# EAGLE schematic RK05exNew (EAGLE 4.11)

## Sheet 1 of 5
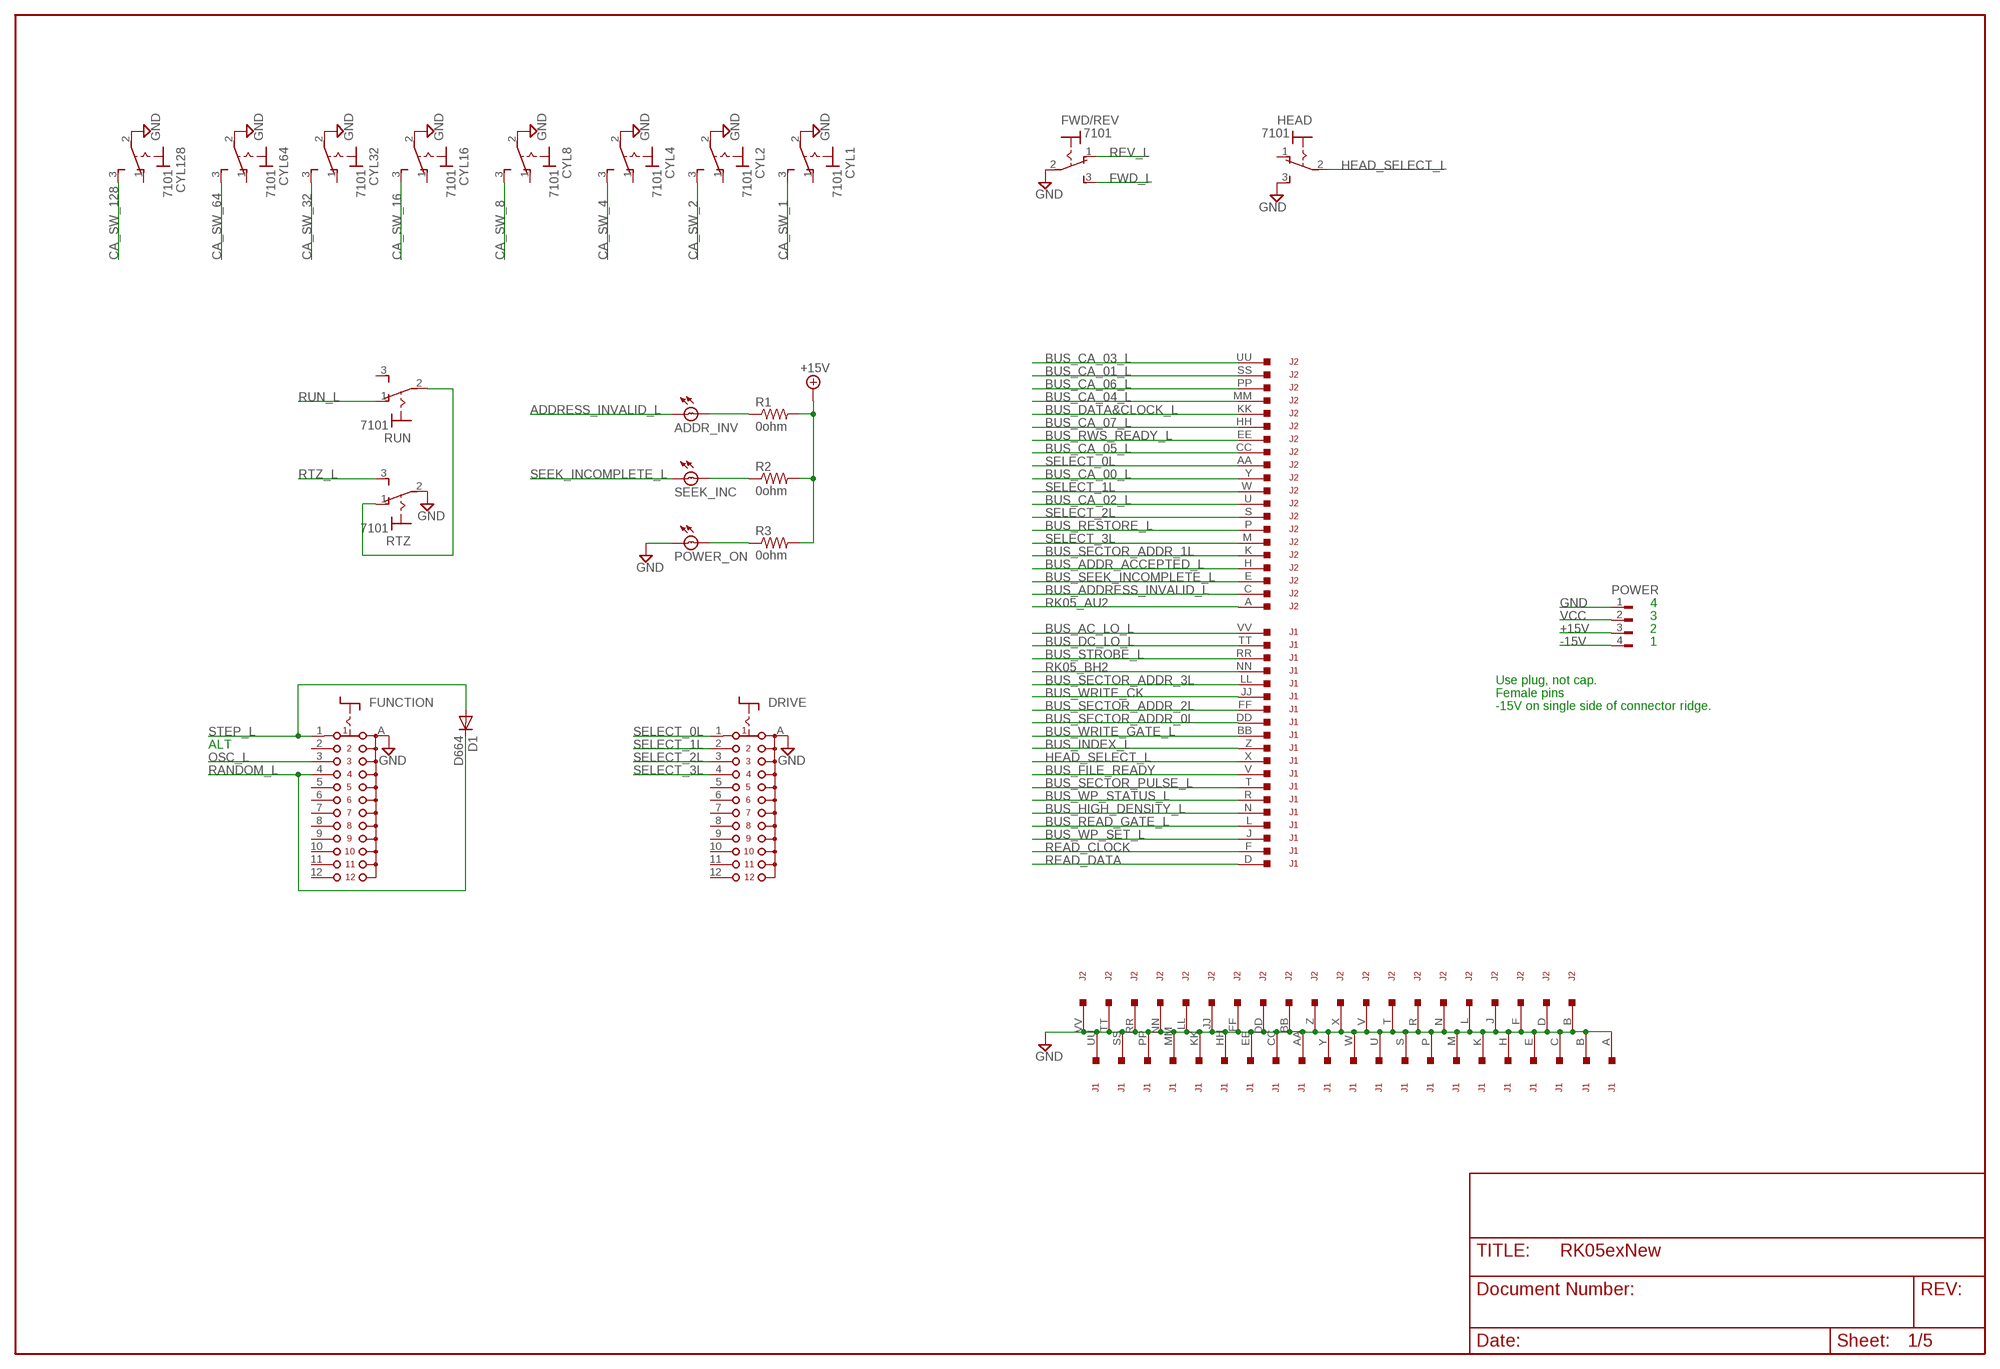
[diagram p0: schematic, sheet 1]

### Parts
ADDR_INV  BULB  [BULB]
CYL1  7101  710X  [7109MD9V3]
CYL2  7101  710X  [7109MD9V3]
CYL4  7101  710X  [7109MD9V3]
CYL8  7101  710X  [7109MD9V3]
CYL16  7101  710X  [7109MD9V3]
CYL32  7101  710X  [7109MD9V3]
CYL64  7101  710X  [7109MD9V3]
CYL128  7101  710X  [7109MD9V3]
D1  D664  1N4148  [DO35-10]
DRIVE  CK101X12  [CK101X12]
FUNCTION  CK101X12  [CK101X12]
FWD/REV  7101  710X  [7109MD9V3]
HEAD  7101  710X  [7109MD9V3]
J1  DEC40PINSV  [DEC40PINV]
J2  DEC40PINSV  [DEC40PINV]
POWER  FLOPPY-4  [FLOPPY-4]
POWER_ON  BULB  [BULB]
R1  0ohm  R-US_0207/10  [0207/10]
R2  0ohm  R-US_0207/10  [0207/10]
R3  0ohm  R-US_0207/10  [0207/10]
RTZ  7101  710X  [7109MD9V3]
RUN  7101  710X  [7109MD9V3]
SEEK_INC  BULB  [BULB]

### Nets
+15V: POWER.3 R1.2 R2.2 R3.2 ; also sheet 3
-15V: POWER.4 ; also sheet 3
ADDRESS_INVALID_L: ADDR_INV.B ; also sheet 3
BUS_AC_LO_L: J1.VV ; also sheet 5
BUS_ADDR_ACCEPTED_L: J2.H ; also sheet 5
BUS_ADDRESS_INVALID_L: J2.C ; also sheet 3,5
BUS_CA_00_L: J2.Y ; also sheet 4,5
BUS_CA_01_L: J2.SS ; also sheet 4,5
BUS_CA_02_L: J2.U ; also sheet 4,5
BUS_CA_03_L: J2.UU ; also sheet 4,5
BUS_CA_04_L: J2.MM ; also sheet 4,5
BUS_CA_05_L: J2.CC ; also sheet 4,5
BUS_CA_06_L: J2.PP ; also sheet 4,5
BUS_CA_07_L: J2.HH ; also sheet 4,5
BUS_DATA&CLOCK_L: J2.KK ; also sheet 2,5
BUS_DC_LO_L: J1.TT ; also sheet 5
BUS_FILE_READY: J1.V ; also sheet 5
BUS_HIGH_DENSITY_L: J1.N ; also sheet 5
BUS_INDEX_L: J1.Z ; also sheet 2,5
BUS_READ_GATE_L: J1.L ; also sheet 5
BUS_RESTORE_L: J2.P ; also sheet 3,5
BUS_RWS_READY_L: J2.EE ; also sheet 3,5
BUS_SECTOR_ADDR_0L: J1.DD ; also sheet 2,5
BUS_SECTOR_ADDR_1L: J2.K ; also sheet 2,5
BUS_SECTOR_ADDR_2L: J1.FF ; also sheet 2,5
BUS_SECTOR_ADDR_3L: J1.LL ; also sheet 2,5
BUS_SECTOR_PULSE_L: J1.T ; also sheet 5
BUS_SEEK_INCOMPLETE_L: J2.E ; also sheet 3,5
BUS_STROBE_L: J1.RR ; also sheet 3,5
BUS_WP_SET_L: J1.J ; also sheet 5
BUS_WP_STATUS_L: J1.R ; also sheet 5
BUS_WRITE_CK: J1.JJ ; also sheet 5
BUS_WRITE_GATE_L: J1.BB ; also sheet 2,5
CA_SW_1: CYL1.3(S) ; also sheet 4
CA_SW_2: CYL2.3(S) ; also sheet 4
CA_SW_4: CYL4.3(S) ; also sheet 4
CA_SW_8: CYL8.3(S) ; also sheet 4
CA_SW_16: CYL16.3(S) ; also sheet 4
CA_SW_32: CYL32.3(S) ; also sheet 4
CA_SW_64: CYL64.3(S) ; also sheet 4
CA_SW_128: CYL128.3(S) ; also sheet 4
FWD_L: FWD/REV.3(S) ; also sheet 3
GND: CYL1.2(P) CYL2.2(P) CYL4.2(P) CYL8.2(P) CYL16.2(P) CYL32.2(P) CYL64.2(P) CYL128.2(P) DRIVE.A FUNCTION.A FWD/REV.2(P) HEAD.3(S) J1.A J1.AA J1.B J1.C J1.CC J1.E J1.EE J1.H J1.HH J1.K J1.KK J1.M J1.MM J1.P J1.PP J1.S J1.SS J1.U J1.UU J1.W J1.Y J2.B J2.BB J2.D J2.DD J2.F J2.FF J2.J J2.JJ J2.L J2.LL J2.N J2.NN J2.R J2.RR J2.T J2.TT J2.V J2.VV J2.X J2.Z POWER.1 POWER_ON.B RTZ.2(P) ; also sheet 2,3,4,5
HEAD_SELECT_L: HEAD.2(P) J1.X ; also sheet 5
N$30: RTZ.1(O) RUN.2(P)
N$37: ADDR_INV.A R1.1
N$38: R2.1 SEEK_INC.A
N$39: POWER_ON.A R3.1
OSC_L: FUNCTION.3 ; also sheet 3
RANDOM_L: D1.C FUNCTION.4 ; also sheet 3
READ_CLOCK: J1.F ; also sheet 5
READ_DATA: J1.D ; also sheet 5
REV_L: FWD/REV.1(O) ; also sheet 3
RK05_AU2: J2.A ; also sheet 5
RK05_BH2: J1.NN ; also sheet 5
RTZ_L: RTZ.3(S) ; also sheet 3
RUN_L: RUN.1(O) ; also sheet 3
SEEK_INCOMPLETE_L: SEEK_INC.B ; also sheet 3
SELECT_0L: DRIVE.1 J2.AA ; also sheet 5
SELECT_1L: DRIVE.2 J2.W ; also sheet 5
SELECT_2L: DRIVE.3 J2.S ; also sheet 5
SELECT_3L: DRIVE.4 J2.M ; also sheet 5
STEP_L: D1.A FUNCTION.1 ; also sheet 3
VCC: POWER.2 ; also sheet 2,3,4,5
Unconnected: CYL1.1(O) CYL2.1(O) CYL4.1(O) CYL8.1(O) CYL16.1(O) CYL32.1(O) CYL64.1(O) CYL128.1(O) DRIVE.5 DRIVE.6 DRIVE.7 DRIVE.8 DRIVE.9 DRIVE.10 DRIVE.11 DRIVE.12 FUNCTION.2 FUNCTION.5 FUNCTION.6 FUNCTION.7 FUNCTION.8 FUNCTION.9 FUNCTION.10 FUNCTION.11 FUNCTION.12 HEAD.1(O) RUN.3(S)

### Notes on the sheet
- 4
- 3
- 2
- 1
- Use plug, not cap.
- Female pins
- -15V on single side of connector ridge.
- ALT

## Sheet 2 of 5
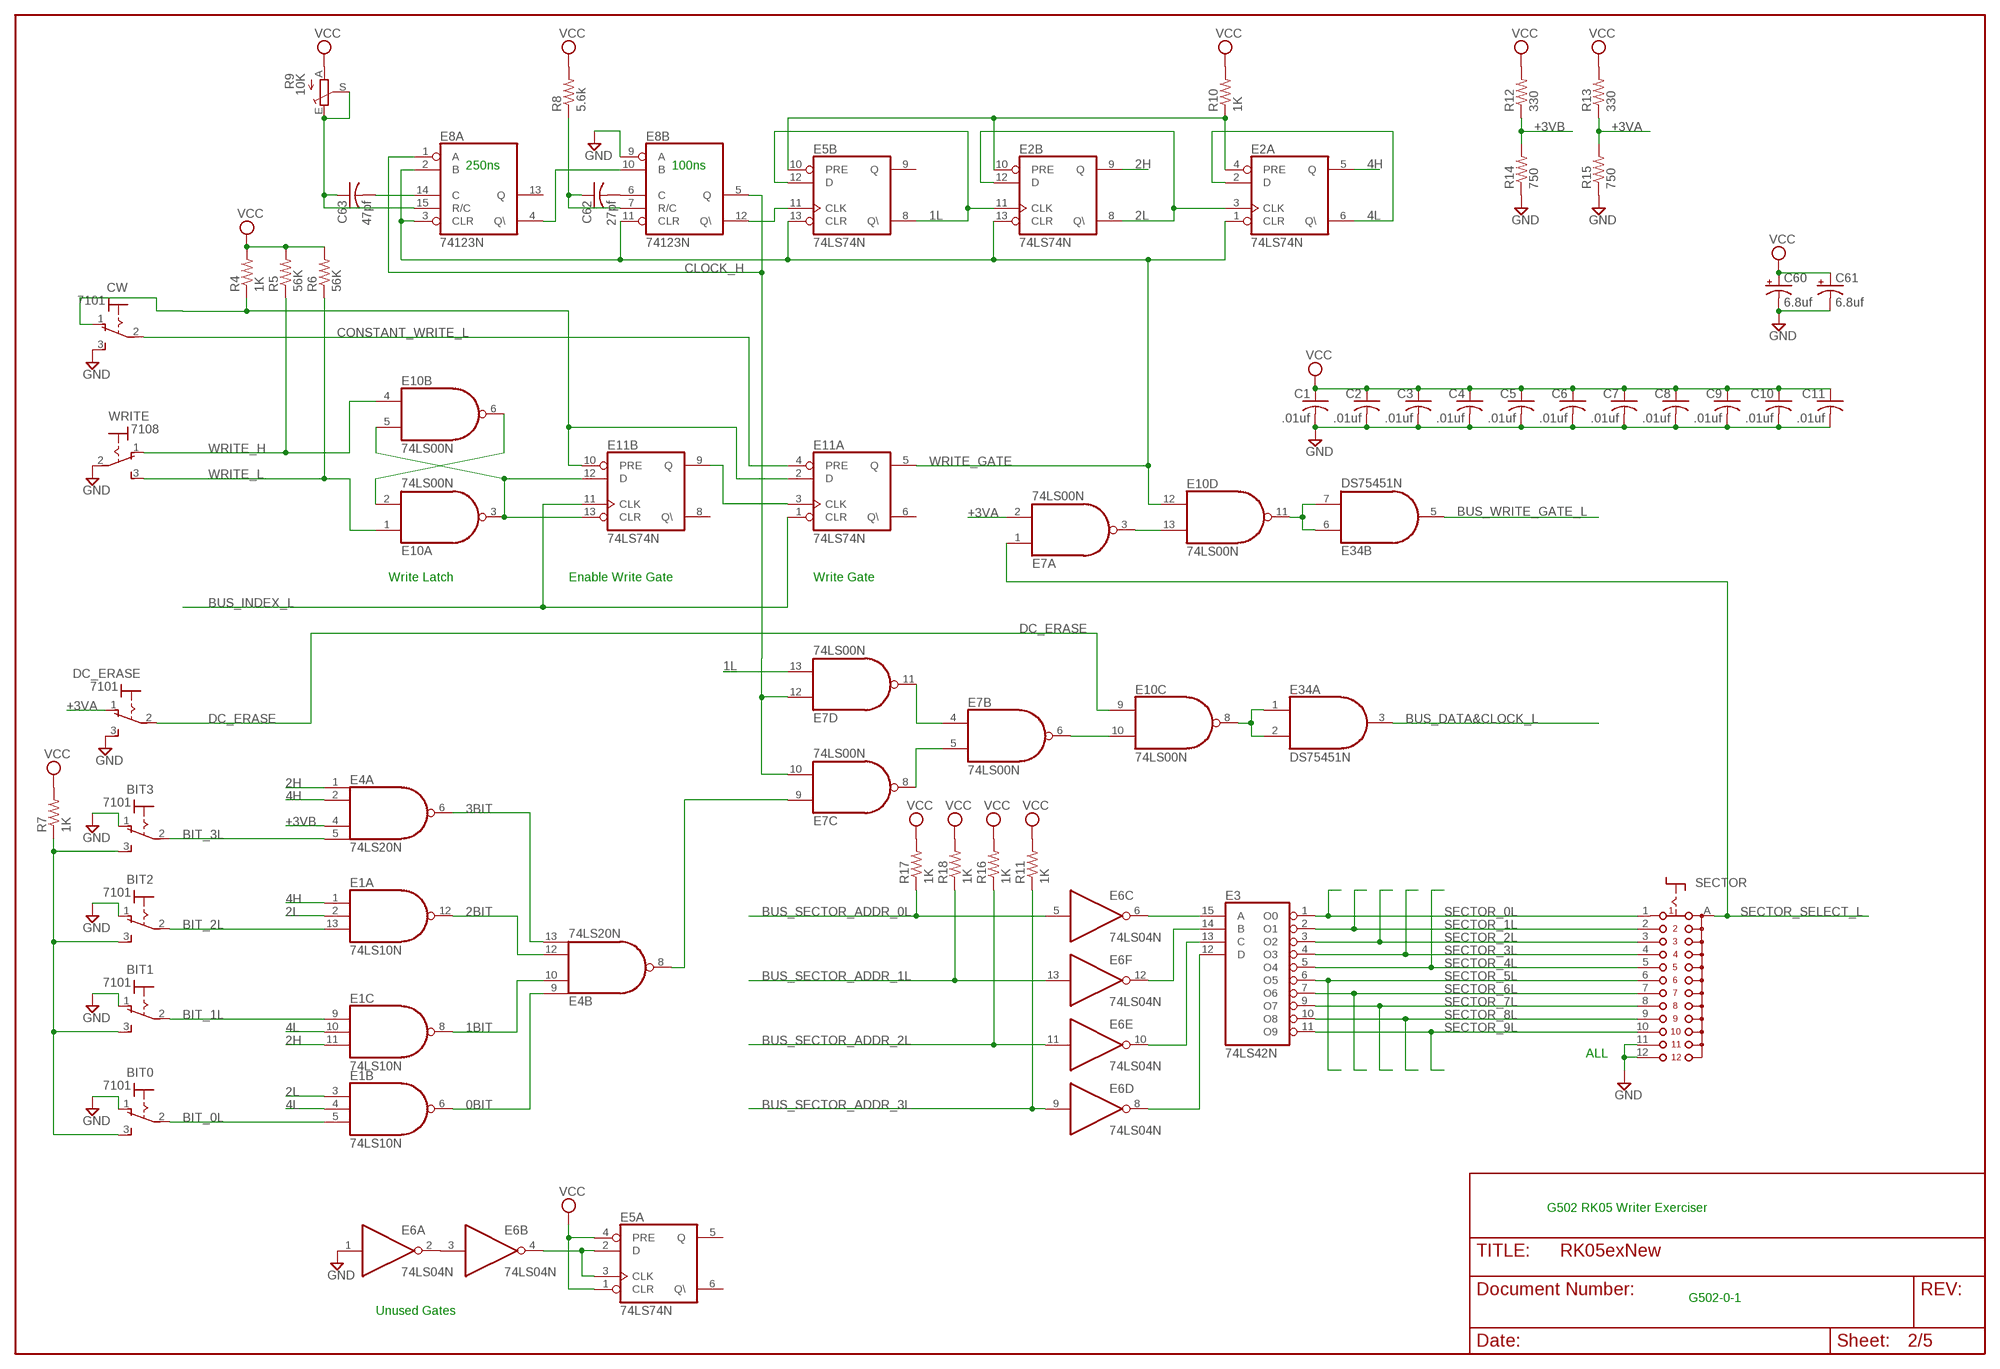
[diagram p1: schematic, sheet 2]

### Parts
BIT0  7101  710X  [7109MD9V3]
BIT1  7101  710X  [7109MD9V3]
BIT2  7101  710X  [7109MD9V3]
BIT3  7101  710X  [7109MD9V3]
C1  .01uf  C-US075-032X103  [C075-032X103]
C2  .01uf  C-US075-032X103  [C075-032X103]
C3  .01uf  C-US075-032X103  [C075-032X103]
C4  .01uf  C-US075-032X103  [C075-032X103]
C5  .01uf  C-US075-032X103  [C075-032X103]
C6  .01uf  C-US075-032X103  [C075-032X103]
C7  .01uf  C-US075-032X103  [C075-032X103]
C8  .01uf  C-US075-032X103  [C075-032X103]
C9  .01uf  C-US075-032X103  [C075-032X103]
C10  .01uf  C-US075-032X103  [C075-032X103]
C11  .01uf  C-US075-032X103  [C075-032X103]
C60  6.8uf  CPOL-USE15-5AXIAL  [E15-5]
C61  6.8uf  CPOL-USE15-5AXIAL  [E15-5]
C62  27pf  C-US075-032X103  [C075-032X103]
C63  47pf  C-US075-032X103  [C075-032X103]
CW  7101  710X  [7109MD9V3]
DC_ERASE  7101  710X  [7109MD9V3]
E1  74LS10N  [DIL14]
E2  74LS74N  [DIL14]
E3  74LS42N  [DIL16]
E4  74LS20N  [DIL14]
E5  74LS74N  [DIL14]
E6  74LS04N  [DIL14]
E7  74LS00N  [DIL14]
E8  74123N  [DIL16]
E10  74LS00N  [DIL14]
E11  74LS74N  [DIL14]
E34  DS75451N  [DIL08]
R4  1K  R-US_0207/10  [0207/10]
R5  56K  R-US_0207/10  [0207/10]
R6  56K  R-US_0207/10  [0207/10]
R7  1K  R-US_0207/10  [0207/10]
R8  5.6k  R-US_0207/10  [0207/10]
R9  10K  TRIM_EU-B90P  [SP19L]
R10  1K  R-US_0207/10  [0207/10]
R11  1K  R-US_0207/10  [0207/10]
R12  330  R-US_0207/10  [0207/10]
R13  330  R-US_0207/10  [0207/10]
R14  750  R-US_0207/10  [0207/10]
R15  750  R-US_0207/10  [0207/10]
R16  1K  R-US_0207/10  [0207/10]
R17  1K  R-US_0207/10  [0207/10]
R18  1K  R-US_0207/10  [0207/10]
SECTOR  CK101X12  [CK101X12]
WRITE  7108  710X  [7109MD9V3]

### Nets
0BIT: E1.6(B:O) E4.9(B:I0)
1.44MHZ: E5.11(B:CLK) E8.12(B:Q\)
1BIT: E1.8(C:O) E4.10(B:I1)
1L: E2.11(B:CLK) E5.8(B:Q\) E5.12(B:D) E7.13(D:I1)
2.88MHZ: E8.4(A:Q\) E8.10(B:B)
2BIT: E1.12(A:O) E4.12(B:I2)
2H: E1.11(C:I2) E2.9(B:Q) E4.1(A:I0)
2L: E1.2(A:I1) E1.3(B:I0) E2.3(A:CLK) E2.8(B:Q\) E2.12(B:D)
3BIT: E4.6(A:O) E4.13(B:I3)
4H: E1.1(A:I0) E2.5(A:Q) E4.2(A:I1)
4L: E1.4(B:I1) E1.10(C:I1) E2.2(A:D) E2.6(A:Q\)
+3VA: DC_ERASE.1(O) E7.2(A:I1) R13.1 R15.2
+3VB: E4.4(A:I2) R12.1 R14.2
+3VC: CW.1(O) E11.2(A:D) E11.10(B:PRE) R4.1
BIT_0L: BIT0.2(P) E1.5(B:I2)
BIT_1L: BIT1.2(P) E1.9(C:I0)
BIT_2L: BIT2.2(P) E1.13(A:I2)
BIT_3L: BIT3.2(P) E4.5(A:I3)
BUS_DATA&CLOCK_L: E34.3(A:O) ; also sheet 1,5
BUS_INDEX_L: E11.1(A:CLR) E11.11(B:CLK) ; also sheet 1,5
BUS_SECTOR_ADDR_0L: E6.5(C:I) R17.1 ; also sheet 1,5
BUS_SECTOR_ADDR_1L: E6.13(F:I) R18.1 ; also sheet 1,5
BUS_SECTOR_ADDR_2L: E6.11(E:I) R16.1 ; also sheet 1,5
BUS_SECTOR_ADDR_3L: E6.9(D:I) R11.1 ; also sheet 1,5
BUS_WRITE_GATE_L: E34.5(B:O) ; also sheet 1,5
CLOCK_H: E7.10(C:I1) E7.12(D:I0) E8.1(A:A) E8.5(B:Q)
CONSTANT_WRITE_L: CW.2(P) E11.4(A:PRE)
DATA_BITS: BIT0.3(S) BIT1.3(S) BIT2.3(S) BIT3.3(S) R7.1
DC_ERASE: DC_ERASE.2(P) E10.9(C:I0)
GND: BIT0.1(O) BIT1.1(O) BIT2.1(O) BIT3.1(O) C1.2 C2.2 C3.2 C4.2 C5.2 C6.2 C7.2 C8.2 C9.2 C10.2 C11.2 C60.- C61.- CW.3(S) DC_ERASE.3(S) E6.1(A:I) E8.9(B:A) R14.1 R15.1 SECTOR.11 SECTOR.12 WRITE.2(P) ; also sheet 1,3,4,5
N$2: E7.6(B:O) E10.10(C:I1)
N$3: E10.3(A:O) E10.5(B:I1) E11.12(B:D) E11.13(B:CLR)
N$4: E10.2(A:I1) E10.6(B:O)
N$5: E2.4(A:PRE) E2.10(B:PRE) E5.10(B:PRE) R10.1
N$6: E7.4(B:I0) E7.11(D:O)
N$7: E7.5(B:I1) E7.8(C:O)
N$8: E11.3(A:CLK) E11.9(B:Q)
N$9: E4.8(B:O) E7.9(C:I0)
N$11: C63.2 E8.14(A:C)
N$12: C62.2 E8.6(B:C)
N$13: C63.1 E8.15(A:R/C) R9.E R9.S
N$14: C62.1 E8.7(B:R/C) R8.1
N$15: E7.3(A:O) E10.13(D:I1)
N$29: E3.15(A) E6.6(C:O)
N$31: E3.14(B) E6.12(F:O)
N$32: E3.13(C) E6.10(E:O)
N$33: E3.12(D) E6.8(D:O)
N$34: E6.2(A:O) E6.3(B:I)
N$36: E5.2(A:D) E5.3(A:CLK) E6.4(B:O)
N$45: E10.8(C:O) E34.1(A:I0) E34.2(A:I1)
N$49: E10.11(D:O) E34.6(B:I0) E34.7(B:I1)
SECTOR_0L: E3.1(O0) SECTOR.1
SECTOR_1L: E3.2(O1) SECTOR.2
SECTOR_2L: E3.3(O2) SECTOR.3
SECTOR_3L: E3.4(O3) SECTOR.4
SECTOR_4L: E3.5(O4) SECTOR.5
SECTOR_5L: E3.6(O5) SECTOR.6
SECTOR_6L: E3.7(O6) SECTOR.7
SECTOR_7L: E3.9(O7) SECTOR.8
SECTOR_8L: E3.10(O8) SECTOR.9
SECTOR_9L: E3.11(O9) SECTOR.10
SECTOR_SELECT_L: E7.1(A:I0) SECTOR.A
VCC: C1.1 C2.1 C3.1 C4.1 C5.1 C6.1 C7.1 C8.1 C9.1 C10.1 C11.1 C60.+ C61.+ E5.1(A:CLR) E5.4(A:PRE) R4.2 R5.2 R6.2 R7.2 R8.2 R9.A R10.2 R11.2 R12.2 R13.2 R16.2 R17.2 R18.2 ; also sheet 1,3,4,5
WRITE_GATE: E2.1(A:CLR) E2.13(B:CLR) E5.13(B:CLR) E8.2(A:B) E8.3(A:CLR) E8.11(B:CLR) E10.12(D:I0) E11.5(A:Q)
WRITE_H: E10.4(B:I0) R5.1 WRITE.1(O)
WRITE_L: E10.1(A:I0) R6.1 WRITE.3(S)
Unconnected: E5.5(A:Q) E5.6(A:Q\) E5.9(B:Q) E8.13(A:Q) E11.6(A:Q\) E11.8(B:Q\)

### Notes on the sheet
- 250ns | 100ns
- Write Latch | Enable Write Gate | Write Gate
- ALL
- G502 RK05 Writer Exerciser
- G502-0-1
- Unused Gates

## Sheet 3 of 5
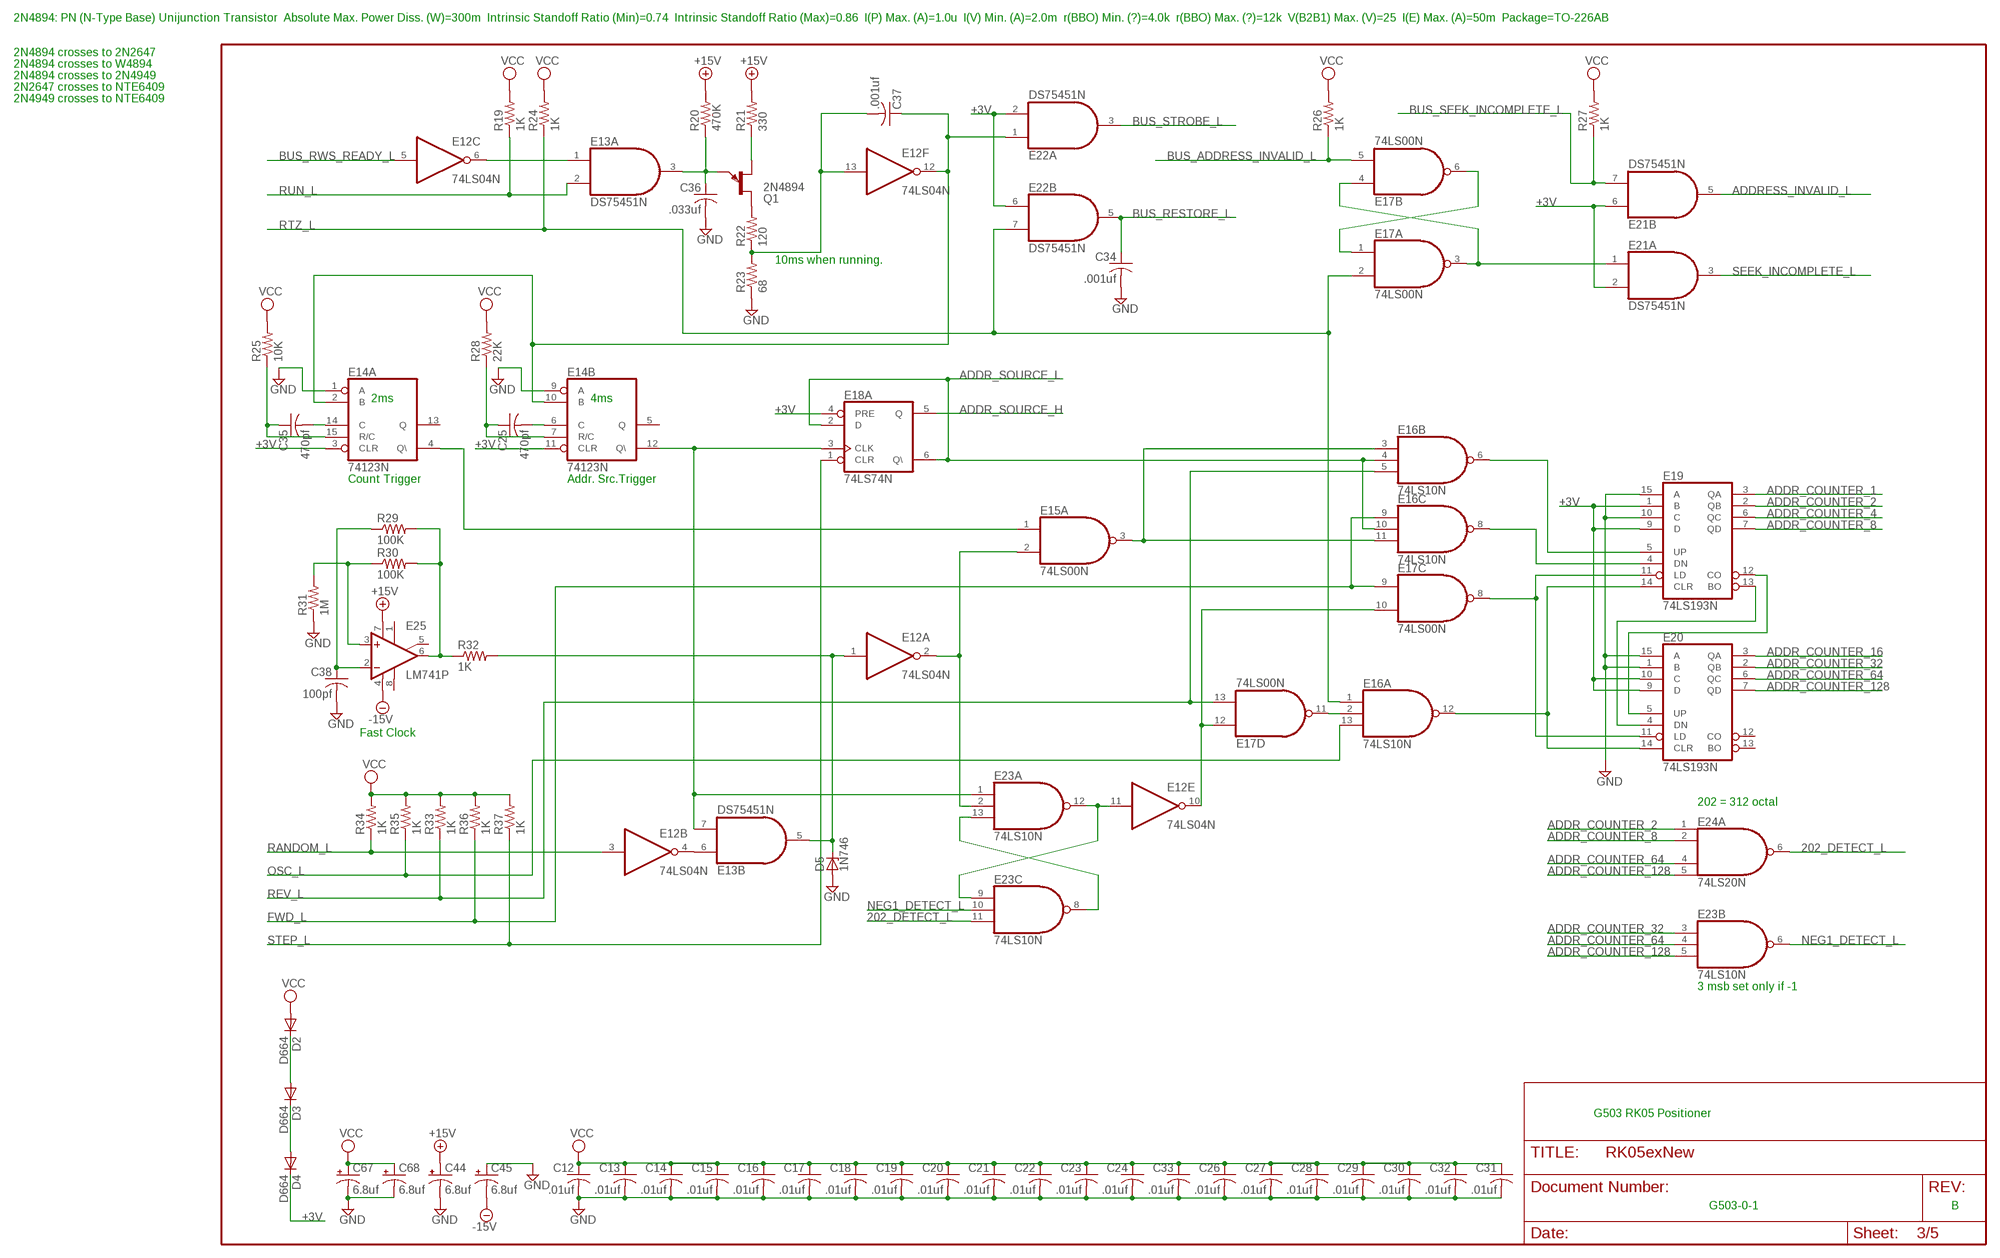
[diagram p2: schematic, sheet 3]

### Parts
C12  .01uf  C-US075-032X103  [C075-032X103]
C13  .01uf  C-US075-032X103  [C075-032X103]
C14  .01uf  C-US075-032X103  [C075-032X103]
C15  .01uf  C-US075-032X103  [C075-032X103]
C16  .01uf  C-US075-032X103  [C075-032X103]
C17  .01uf  C-US075-032X103  [C075-032X103]
C18  .01uf  C-US075-032X103  [C075-032X103]
C19  .01uf  C-US075-032X103  [C075-032X103]
C20  .01uf  C-US075-032X103  [C075-032X103]
C21  .01uf  C-US075-032X103  [C075-032X103]
C22  .01uf  C-US075-032X103  [C075-032X103]
C23  .01uf  C-US075-032X103  [C075-032X103]
C24  .01uf  C-US075-032X103  [C075-032X103]
C25  470pf  C-US075-032X103  [C075-032X103]
C26  .01uf  C-US075-032X103  [C075-032X103]
C27  .01uf  C-US075-032X103  [C075-032X103]
C28  .01uf  C-US075-032X103  [C075-032X103]
C29  .01uf  C-US075-032X103  [C075-032X103]
C30  .01uf  C-US075-032X103  [C075-032X103]
C31  .01uf  C-US075-032X103  [C075-032X103]
C32  .01uf  C-US075-032X103  [C075-032X103]
C33  .01uf  C-US075-032X103  [C075-032X103]
C34  .001uf  C-US075-032X103  [C075-032X103]
C35  470pf  C-US075-032X103  [C075-032X103]
C36  .033uf  C-US075-032X103  [C075-032X103]
C37  .001uf  C-US075-032X103  [C075-032X103]
C38  100pf  C-US075-032X103  [C075-032X103]
C44  6.8uf  CPOL-USE15-5AXIAL  [E15-5]
C45  6.8uf  CPOL-USE15-5AXIAL  [E15-5]
C67  6.8uf  CPOL-USE15-5AXIAL  [E15-5]
C68  6.8uf  CPOL-USE15-5AXIAL  [E15-5]
D2  D664  1N4148  [DO35-10]
D3  D664  1N4148  [DO35-10]
D4  D664  1N4148  [DO35-10]
D5  1N746  ZENER-DIODEDO35Z10  [DO35Z10]
E12  74LS04N  [DIL14]
E13  DS75451N  [DIL08]
E14  74123N  [DIL16]
E15  74LS00N  [DIL14]
E16  74LS10N  [DIL14]
E17  74LS00N  [DIL14]
E18  74LS74N  [DIL14]
E19  74LS193N  [DIL16]
E20  74LS193N  [DIL16]
E21  DS75451N  [DIL08]
E22  DS75451N  [DIL08]
E23  74LS10N  [DIL14]
E24  74LS20N  [DIL14]
E25  LM741P  [DIL08]
Q1  2N4894  2N4870  [TO92E]
R19  1K  R-US_0207/10  [0207/10]
R20  470K  R-US_0207/10  [0207/10]
R21  330  R-US_0207/10  [0207/10]
R22  120  R-US_0207/10  [0207/10]
R23  68  R-US_0207/10  [0207/10]
R24  1K  R-US_0207/10  [0207/10]
R25  10K  R-US_0207/10  [0207/10]
R26  1K  R-US_0207/10  [0207/10]
R27  1K  R-US_0207/10  [0207/10]
R28  22K  R-US_0207/10  [0207/10]
R29  100K  R-US_0207/10  [0207/10]
R30  100K  R-US_0207/10  [0207/10]
R31  1M  R-US_0207/10  [0207/10]
R32  1K  R-US_0207/10  [0207/10]
R33  1K  R-US_0207/10  [0207/10]
R34  1K  R-US_0207/10  [0207/10]
R35  1K  R-US_0207/10  [0207/10]
R36  1K  R-US_0207/10  [0207/10]
R37  1K  R-US_0207/10  [0207/10]

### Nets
202_DETECT_L: E23.11(C:I2) E24.6(A:O)
+3V: D4.C E14.3(A:CLR) E14.11(B:CLR) E18.4(A:PRE) E19.1(B) E19.9(D) E20.9(D) E20.10(C) E21.2(A:I1) E21.6(B:I0) E22.2(A:I1) E22.6(B:I0)
+15V: C44.+ E25.7(V+) R20.2 R21.2 ; also sheet 1
-15V: C45.- E25.4(V-) ; also sheet 1
ADDR_COUNTER_1: E19.3(QA) ; also sheet 4
ADDR_COUNTER_2: E19.2(QB) E24.1(A:I0) ; also sheet 4
ADDR_COUNTER_4: E19.6(QC) ; also sheet 4
ADDR_COUNTER_8: E19.7(QD) E24.2(A:I1) ; also sheet 4
ADDR_COUNTER_16: E20.3(QA) ; also sheet 4
ADDR_COUNTER_32: E20.2(QB) E23.3(B:I0) ; also sheet 4
ADDR_COUNTER_64: E20.6(QC) E23.4(B:I1) E24.4(A:I2) ; also sheet 4
ADDR_COUNTER_128: E20.7(QD) E23.5(B:I2) E24.5(A:I3) ; also sheet 4
ADDR_SOURCE_H: E18.5(A:Q) ; also sheet 4
ADDR_SOURCE_L: E16.4(B:I1) E16.10(C:I1) E18.2(A:D) E18.6(A:Q\) ; also sheet 4
ADDRESS_INVALID_L: E21.5(B:O) ; also sheet 1
BUS_ADDRESS_INVALID_L: E17.5(B:I1) R26.1 ; also sheet 1,5
BUS_RESTORE_L: C34.1 E22.5(B:O) ; also sheet 1,5
BUS_RWS_READY_L: E12.5(C:I) ; also sheet 1,5
BUS_SEEK_INCOMPLETE_L: E21.7(B:I1) R27.1 ; also sheet 1,5
BUS_STROBE_L: E22.3(A:O) ; also sheet 1,5
FWD_L: E16.9(C:I0) E17.9(C:I0) R36.1 ; also sheet 1
GND: C12.2 C13.2 C14.2 C15.2 C16.2 C17.2 C18.2 C19.2 C20.2 C21.2 C22.2 C23.2 C24.2 C26.2 C27.2 C28.2 C29.2 C30.2 C31.2 C32.2 C33.2 C34.2 C36.2 C38.2 C44.- C45.+ C67.- C68.- D5.A E14.1(A:A) E14.9(B:A) E19.10(C) E19.15(A) E20.1(B) E20.15(A) R23.1 R31.1 ; also sheet 1,2,4,5
N$1: E12.6(C:O) E13.1(A:I0)
N$10: C36.1 E13.3(A:O) Q1.E R20.1
N$16: Q1.B1 R21.1
N$17: Q1.B2 R22.2
N$18: C37.2 E12.13(F:I) R22.1 R23.2
N$19: C37.1 E12.12(F:O) E14.2(A:B) E14.10(B:B) E22.1(A:I0)
N$20: E17.1(A:I0) E17.6(B:O)
N$21: E17.3(A:O) E17.4(B:I0) E21.1(A:I0)
N$22: C35.1 E14.15(A:R/C) R25.1
N$23: C35.2 E14.14(A:C)
N$24: C25.1 E14.7(B:R/C) R28.1
N$25: C25.2 E14.6(B:C)
N$26: E19.13(BO) E20.4(DN)
N$27: E19.12(CO) E20.5(UP)
N$28: E16.6(B:O) E19.5(UP)
N$35: E16.8(C:O) E19.4(DN)
N$40: E17.8(C:O) E19.11(LD) E20.11(LD)
N$41: E16.12(A:O) E19.14(CLR) E20.14(CLR)
N$42: C38.1 E25.2(-IN) R29.1
N$43: E25.6(OUT) R29.2 R30.2 R32.1
N$44: E25.3(+IN) R30.1 R31.2
N$46: E12.2(A:O) E15.2(A:I1) E23.2(A:I1)
N$47: E14.4(A:Q\) E15.1(A:I0)
N$48: D2.C D3.A
N$53: D3.C D4.A
N$55: E12.4(B:O) E13.6(B:I0)
N$57: E13.7(B:I1) E14.12(B:Q\) E18.3(A:CLK) E23.1(A:I0)
N$58: D5.C E12.1(A:I) E13.5(B:O) R32.2
N$59: E15.3(A:O) E16.3(B:I0) E16.11(C:I2)
N$60: E23.8(C:O) E23.13(A:I2)
N$61: E12.11(E:I) E23.9(C:I0) E23.12(A:O)
N$62: E16.2(A:I1) E17.11(D:O)
N$63: E12.10(E:O) E17.10(C:I1) E17.12(D:I0)
NEG1_DETECT_L: E23.6(B:O) E23.10(C:I1)
OSC_L: E16.13(A:I2) R35.1 ; also sheet 1
RANDOM_L: E12.3(B:I) R34.1 ; also sheet 1
REV_L: E16.5(B:I2) E17.13(D:I1) R33.1 ; also sheet 1
RTZ_L: E16.1(A:I0) E17.2(A:I1) E22.7(B:I1) R24.1 ; also sheet 1
RUN_L: E13.2(A:I1) R19.1 ; also sheet 1
SEEK_INCOMPLETE_L: E21.3(A:O) ; also sheet 1
STEP_L: E18.1(A:CLR) R37.1 ; also sheet 1
VCC: C12.1 C13.1 C14.1 C15.1 C16.1 C17.1 C18.1 C19.1 C20.1 C21.1 C22.1 C23.1 C24.1 C26.1 C27.1 C28.1 C29.1 C30.1 C31.1 C32.1 C33.1 C67.+ C68.+ D2.A R19.2 R24.2 R25.2 R26.2 R27.2 R28.2 R33.2 R34.2 R35.2 R36.2 R37.2 ; also sheet 1,2,4,5
Unconnected: E14.5(B:Q) E14.13(A:Q) E20.12(CO) E20.13(BO) E25.1(ON1) E25.5(ON2) E25.8(OPT)

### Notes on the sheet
- 2N4894: PN (N-Type Base) Unijunction Transistor  Absolute Max. Power Diss. (W)=300m  Intrinsic Standoff Ratio (Min)=0.74  Intrinsic Standoff Ratio (Max)=0.86  I(P) Max. (A)=1.0u  I(V) Min. (A)=2.0m  r(BBO) Min. (?)=4.0k  r(BBO) Max. (?)=12k  V(B2B1) Max. (V)=25  I(E) Max. (A)=50m  Package=TO-226AB
- 2N4894 crosses to 2N2647
- 2N4894 crosses to W4894
- 2N4894 crosses to 2N4949
- 2N2647 crosses to NTE6409
- 2N4949 crosses to NTE6409
- 10ms when running.
- 2ms | 4ms
- Count Trigger | Addr. Src.Trigger
- Fast Clock
- 202 = 312 octal
- 3 msb set only if -1
- G503 RK05 Positioner
- G503-0-1 | B

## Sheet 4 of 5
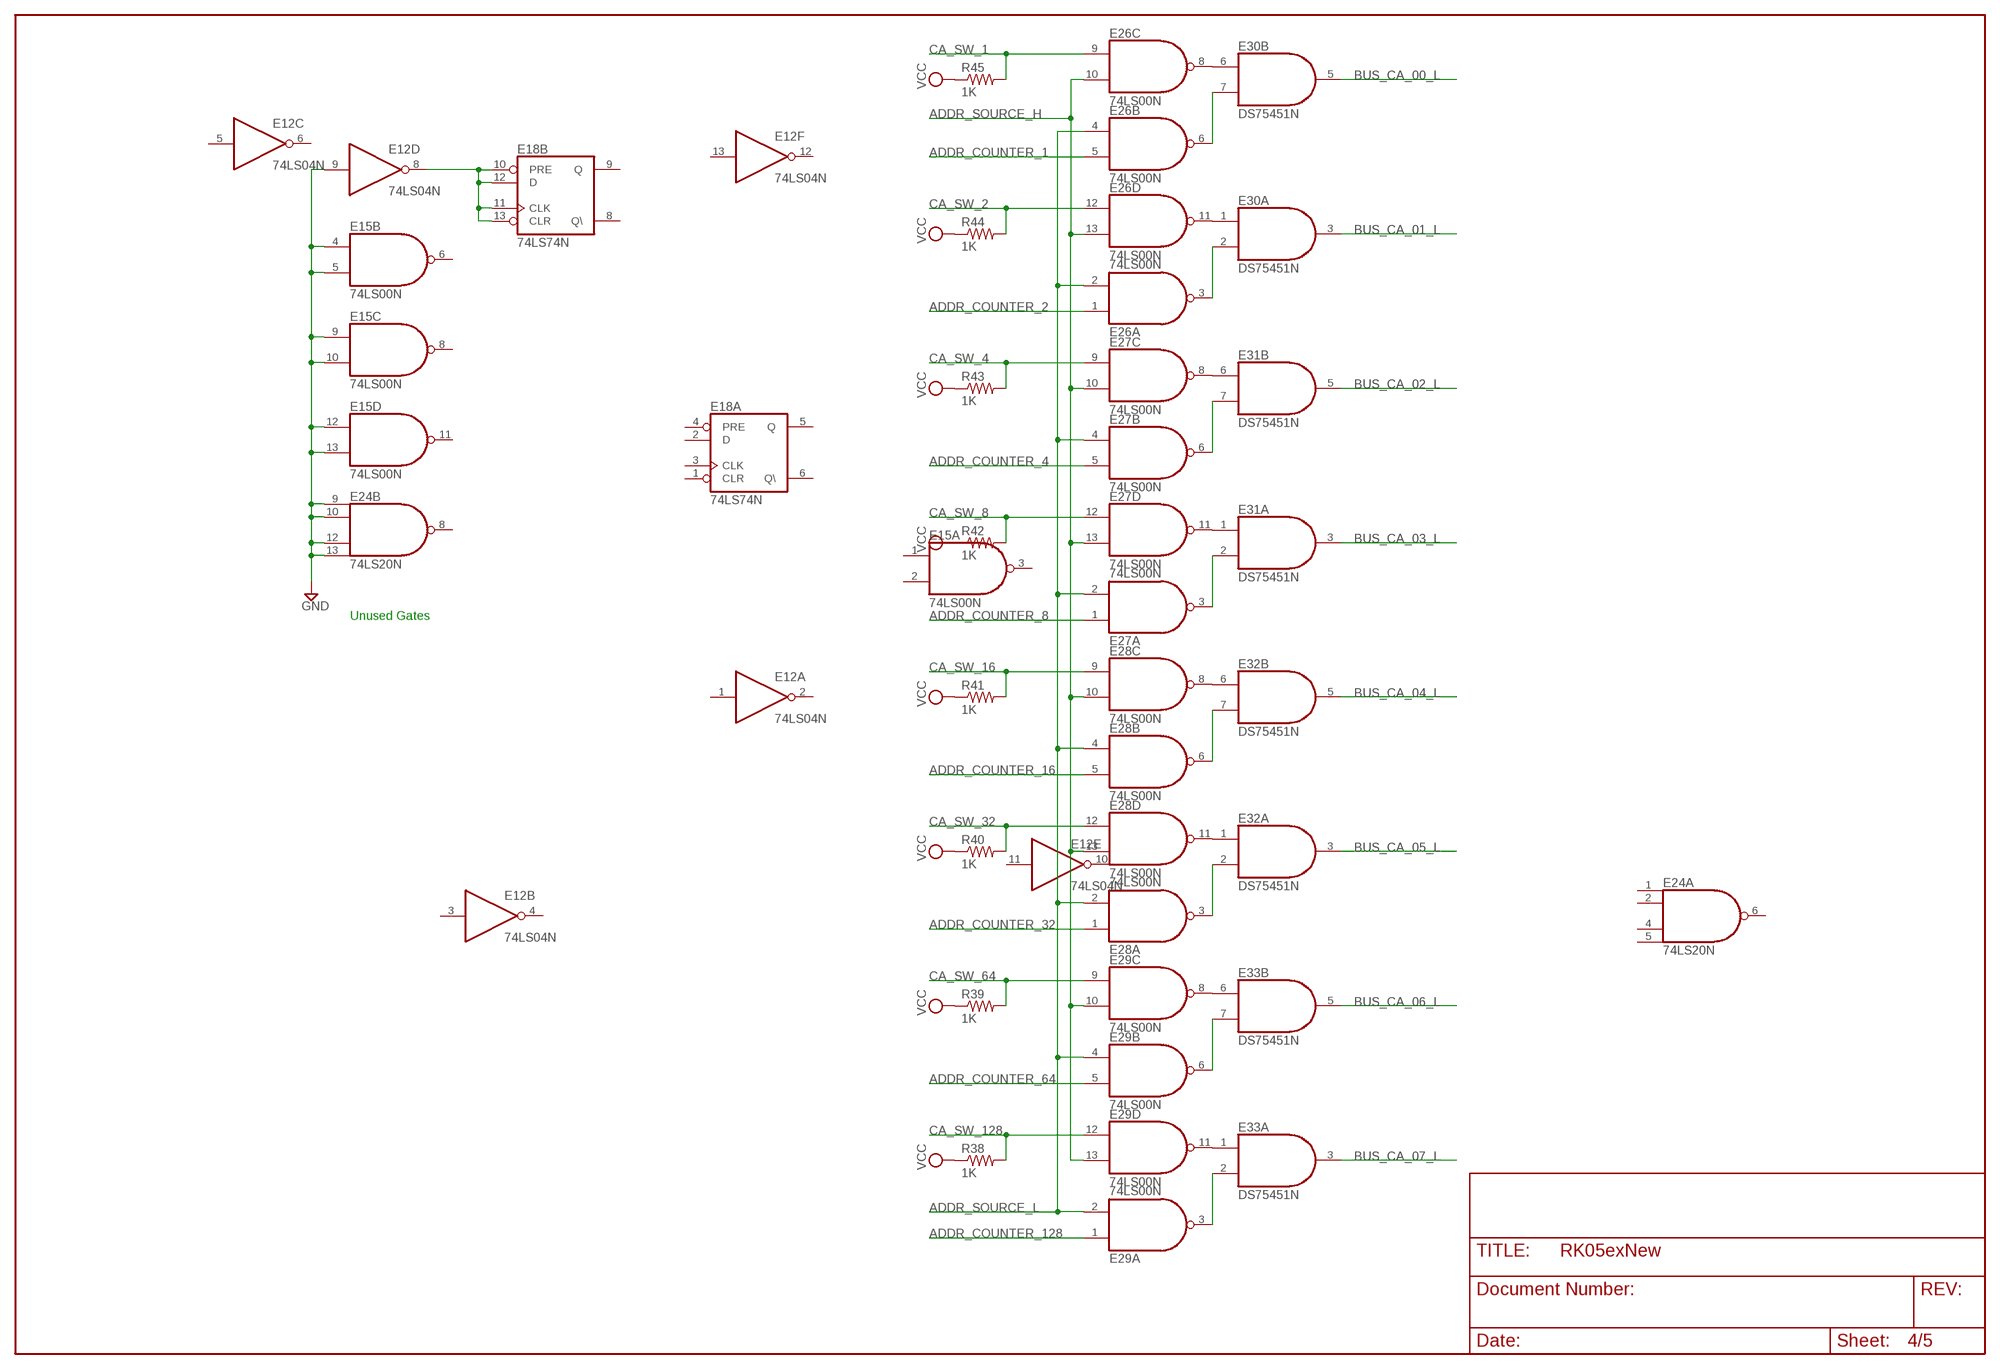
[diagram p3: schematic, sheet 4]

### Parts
E26  74LS00N  [DIL14]
E27  74LS00N  [DIL14]
E28  74LS00N  [DIL14]
E29  74LS00N  [DIL14]
E30  DS75451N  [DIL08]
E31  DS75451N  [DIL08]
E32  DS75451N  [DIL08]
E33  DS75451N  [DIL08]
R38  1K  R-US_0207/10  [0207/10]
R39  1K  R-US_0207/10  [0207/10]
R40  1K  R-US_0207/10  [0207/10]
R41  1K  R-US_0207/10  [0207/10]
R42  1K  R-US_0207/10  [0207/10]
R43  1K  R-US_0207/10  [0207/10]
R44  1K  R-US_0207/10  [0207/10]
R45  1K  R-US_0207/10  [0207/10]

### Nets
ADDR_COUNTER_1: E26.5(B:I1) ; also sheet 3
ADDR_COUNTER_2: E26.1(A:I0) ; also sheet 3
ADDR_COUNTER_4: E27.5(B:I1) ; also sheet 3
ADDR_COUNTER_8: E27.1(A:I0) ; also sheet 3
ADDR_COUNTER_16: E28.5(B:I1) ; also sheet 3
ADDR_COUNTER_32: E28.1(A:I0) ; also sheet 3
ADDR_COUNTER_64: E29.5(B:I1) ; also sheet 3
ADDR_COUNTER_128: E29.1(A:I0) ; also sheet 3
ADDR_SOURCE_H: E26.10(C:I1) E26.13(D:I1) E27.10(C:I1) E27.13(D:I1) E28.10(C:I1) E28.13(D:I1) E29.10(C:I1) E29.13(D:I1) ; also sheet 3
ADDR_SOURCE_L: E26.2(A:I1) E26.4(B:I0) E27.2(A:I1) E27.4(B:I0) E28.2(A:I1) E28.4(B:I0) E29.2(A:I1) E29.4(B:I0) ; also sheet 3
BUS_CA_00_L: E30.5(B:O) ; also sheet 1,5
BUS_CA_01_L: E30.3(A:O) ; also sheet 1,5
BUS_CA_02_L: E31.5(B:O) ; also sheet 1,5
BUS_CA_03_L: E31.3(A:O) ; also sheet 1,5
BUS_CA_04_L: E32.5(B:O) ; also sheet 1,5
BUS_CA_05_L: E32.3(A:O) ; also sheet 1,5
BUS_CA_06_L: E33.5(B:O) ; also sheet 1,5
BUS_CA_07_L: E33.3(A:O) ; also sheet 1,5
CA_SW_1: E26.9(C:I0) R45.2 ; also sheet 1
CA_SW_2: E26.12(D:I0) R44.2 ; also sheet 1
CA_SW_4: E27.9(C:I0) R43.2 ; also sheet 1
CA_SW_8: E27.12(D:I0) R42.2 ; also sheet 1
CA_SW_16: E28.9(C:I0) R41.2 ; also sheet 1
CA_SW_32: E28.12(D:I0) R40.2 ; also sheet 1
CA_SW_64: E29.9(C:I0) R39.2 ; also sheet 1
CA_SW_128: E29.12(D:I0) R38.2 ; also sheet 1
GND: E12.9(D:I) E15.4(B:I0) E15.5(B:I1) E15.9(C:I0) E15.10(C:I1) E15.12(D:I0) E15.13(D:I1) E24.9(B:I0) E24.10(B:I1) E24.12(B:I2) E24.13(B:I3) ; also sheet 1,2,3,5
N$64: E26.6(B:O) E30.7(B:I1)
N$65: E26.8(C:O) E30.6(B:I0)
N$66: E26.3(A:O) E30.2(A:I1)
N$67: E26.11(D:O) E30.1(A:I0)
N$68: E27.8(C:O) E31.6(B:I0)
N$69: E27.6(B:O) E31.7(B:I1)
N$70: E27.11(D:O) E31.1(A:I0)
N$71: E27.3(A:O) E31.2(A:I1)
N$72: E28.6(B:O) E32.7(B:I1)
N$73: E28.3(A:O) E32.2(A:I1)
N$75: E29.6(B:O) E33.7(B:I1)
N$76: E29.3(A:O) E33.2(A:I1)
N$77: E29.11(D:O) E33.1(A:I0)
N$78: E29.8(C:O) E33.6(B:I0)
N$80: E28.11(D:O) E32.1(A:I0)
N$81: E28.8(C:O) E32.6(B:I0)
N$82: E12.8(D:O) E18.10(B:PRE) E18.11(B:CLK) E18.12(B:D) E18.13(B:CLR)
VCC: R38.1 R39.1 R40.1 R41.1 R42.1 R43.1 R44.1 R45.1 ; also sheet 1,2,3,5
Unconnected: E15.6(B:O) E15.8(C:O) E15.11(D:O) E18.8(B:Q\) E18.9(B:Q) E24.8(B:O)

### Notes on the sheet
- Unused Gates

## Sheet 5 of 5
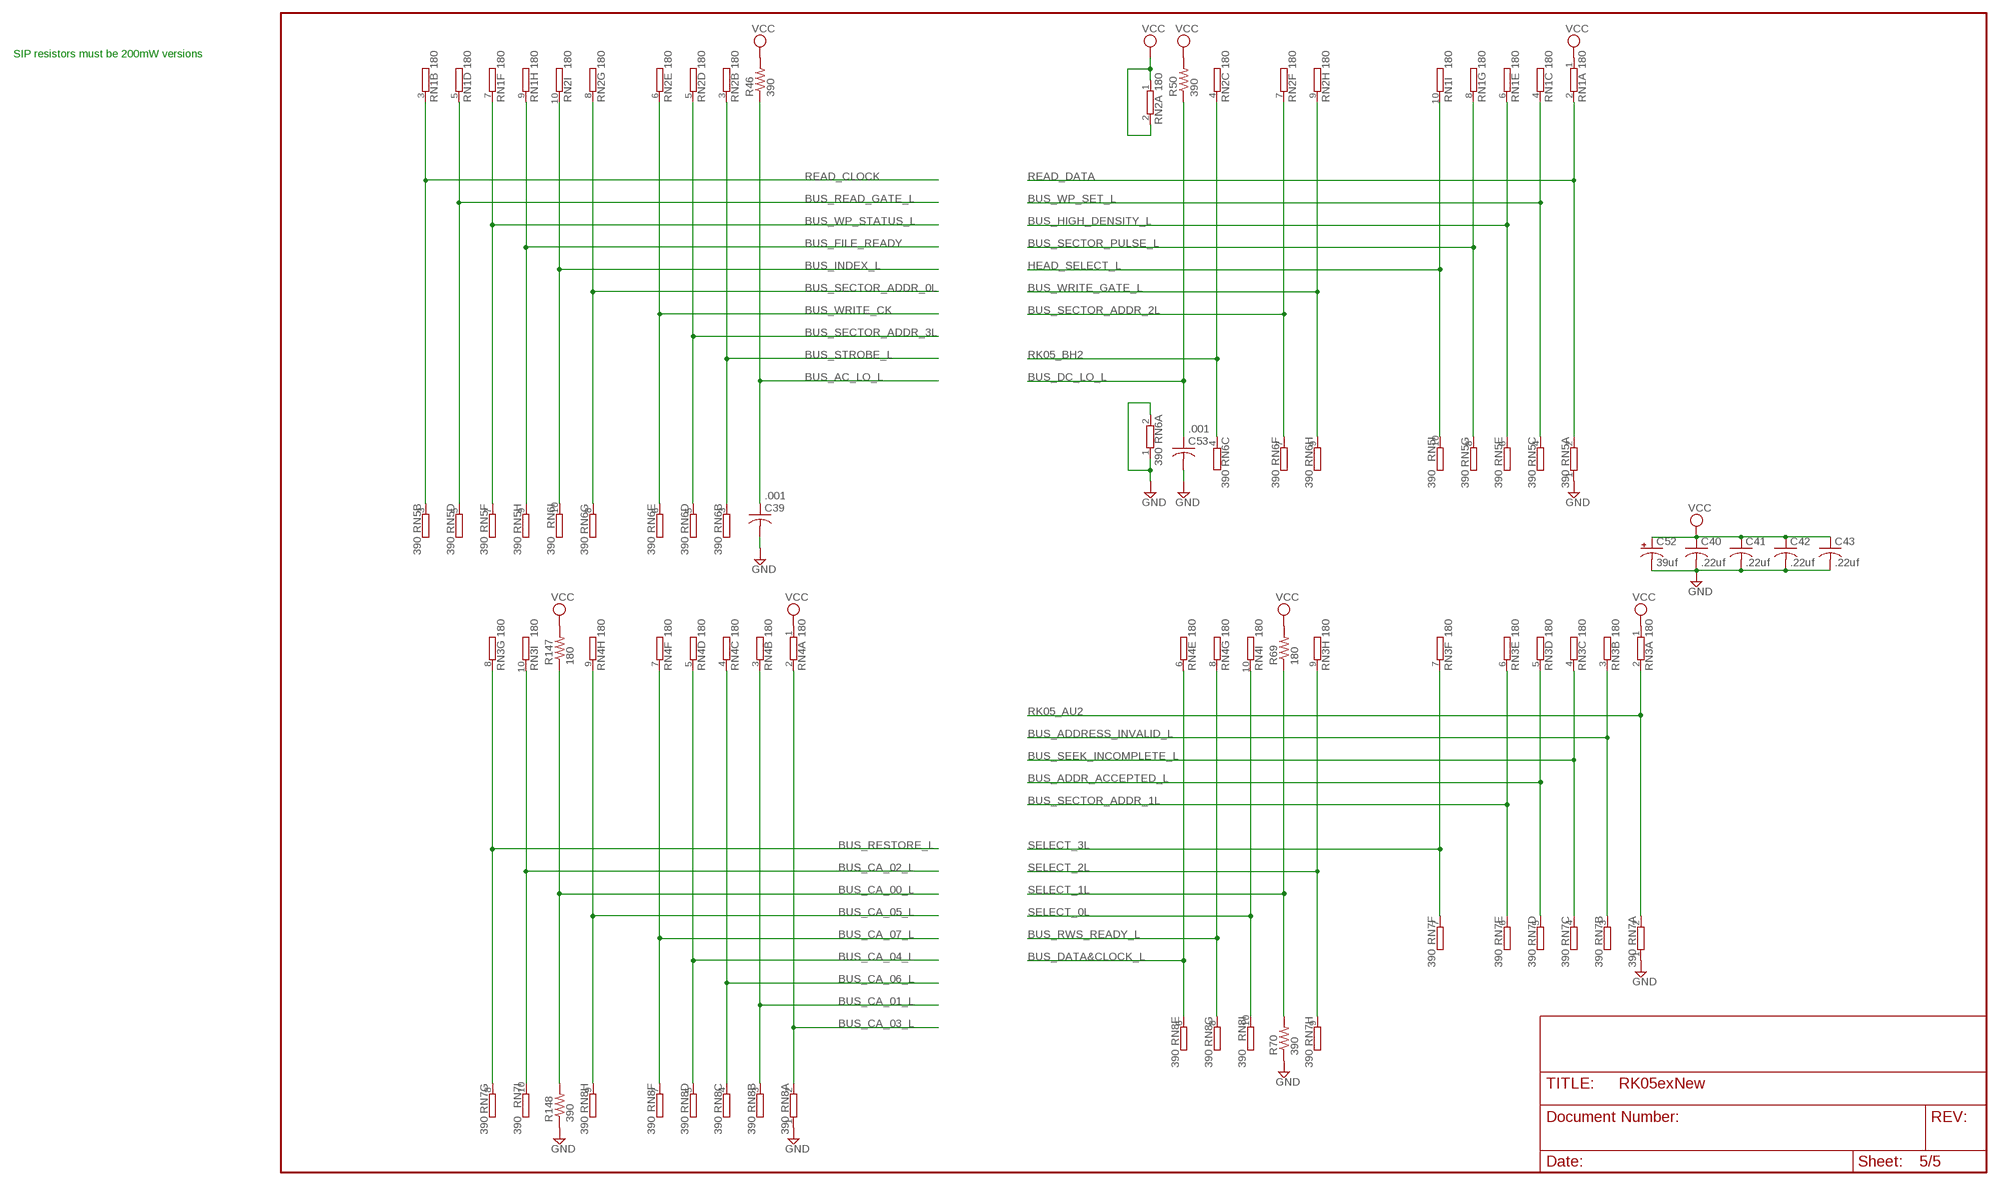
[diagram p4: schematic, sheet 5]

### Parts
C39  .001  C-US050-025X075  [C050-025X075]
C40  .22uf  C-US050-025X075  [C050-025X075]
C41  .22uf  C-US050-025X075  [C050-025X075]
C42  .22uf  C-US050-025X075  [C050-025X075]
C43  .22uf  C-US075-032X103  [C075-032X103]
C52  39uf  CPOL-USE15-5AXIAL  [E15-5]
C53  .001  C-US075-032X103  [C075-032X103]
R46  390  R-US_0207/10  [0207/10]
R50  390  R-US_0207/10  [0207/10]
R69  180  R-US_0207/10  [0207/10]
R70  390  R-US_0207/10  [0207/10]
R147  180  R-US_0207/10  [0207/10]
R148  390  R-US_0207/10  [0207/10]
RN1  180  GE09R  [SIL10]
RN2  180  GE09R  [SIL10]
RN3  180  GE09R  [SIL10]
RN4  180  GE09R  [SIL10]
RN5  390  GE09R  [SIL10]
RN6  390  GE09R  [SIL10]
RN7  390  GE09R  [SIL10]
RN8  390  GE09R  [SIL10]

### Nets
BUS_AC_LO_L: C39.1 R46.1 ; also sheet 1
BUS_ADDR_ACCEPTED_L: RN3.5 RN7.5 ; also sheet 1
BUS_ADDRESS_INVALID_L: RN3.3 RN7.3 ; also sheet 1,3
BUS_CA_00_L: R147.1 R148.2 ; also sheet 1,4
BUS_CA_01_L: RN4.3 RN8.3 ; also sheet 1,4
BUS_CA_02_L: RN3.10 RN7.10 ; also sheet 1,4
BUS_CA_03_L: RN4.2 RN8.2 ; also sheet 1,4
BUS_CA_04_L: RN4.5 RN8.5 ; also sheet 1,4
BUS_CA_05_L: RN4.9 RN8.9 ; also sheet 1,4
BUS_CA_06_L: RN4.4 RN8.4 ; also sheet 1,4
BUS_CA_07_L: RN4.7 RN8.7 ; also sheet 1,4
BUS_DATA&CLOCK_L: RN4.6 RN8.6 ; also sheet 1,2
BUS_DC_LO_L: C53.1 R50.1 ; also sheet 1
BUS_FILE_READY: RN1.9 RN5.9 ; also sheet 1
BUS_HIGH_DENSITY_L: RN1.6 RN5.6 ; also sheet 1
BUS_INDEX_L: RN2.10 RN6.10 ; also sheet 1,2
BUS_READ_GATE_L: RN1.5 RN5.5 ; also sheet 1
BUS_RESTORE_L: RN3.8 RN7.8 ; also sheet 1,3
BUS_RWS_READY_L: RN4.8 RN8.8 ; also sheet 1,3
BUS_SECTOR_ADDR_0L: RN2.8 RN6.8 ; also sheet 1,2
BUS_SECTOR_ADDR_1L: RN3.6 RN7.6 ; also sheet 1,2
BUS_SECTOR_ADDR_2L: RN2.7 RN6.7 ; also sheet 1,2
BUS_SECTOR_ADDR_3L: RN2.5 RN6.5 ; also sheet 1,2
BUS_SECTOR_PULSE_L: RN1.8 RN5.8 ; also sheet 1
BUS_SEEK_INCOMPLETE_L: RN3.4 RN7.4 ; also sheet 1,3
BUS_STROBE_L: RN2.3 RN6.3 ; also sheet 1,3
BUS_WP_SET_L: RN1.4 RN5.4 ; also sheet 1
BUS_WP_STATUS_L: RN1.7 RN5.7 ; also sheet 1
BUS_WRITE_CK: RN2.6 RN6.6 ; also sheet 1
BUS_WRITE_GATE_L: RN2.9 RN6.9 ; also sheet 1,2
GND: C39.2 C40.2 C41.2 C42.2 C43.2 C52.- C53.2 R70.1 R148.1 RN5.1 RN6.1 RN6.2 RN7.1 RN8.1 ; also sheet 1,2,3,4
HEAD_SELECT_L: RN1.10 RN5.10 ; also sheet 1
READ_CLOCK: RN1.3 RN5.3 ; also sheet 1
READ_DATA: RN1.2 RN5.2 ; also sheet 1
RK05_AU2: RN3.2 RN7.2 ; also sheet 1
RK05_BH2: RN2.4 RN6.4 ; also sheet 1
SELECT_0L: RN4.10 RN8.10 ; also sheet 1
SELECT_1L: R69.1 R70.2 ; also sheet 1
SELECT_2L: RN3.9 RN7.9 ; also sheet 1
SELECT_3L: RN3.7 RN7.7 ; also sheet 1
VCC: C40.1 C41.1 C42.1 C43.1 C52.+ R46.2 R50.2 R69.2 R147.2 RN1.1 RN2.1 RN2.2 RN3.1 RN4.1 ; also sheet 1,2,3,4

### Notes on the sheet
- SIP resistors must be 200mW versions

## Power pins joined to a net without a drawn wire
GND: BIT0.NC@1(GND) BIT0.NC@2(GND) BIT0.NC@3(GND) BIT0.NC@4(GND) BIT0.NC@5(GND) BIT0.NC@6(GND) BIT0.NC@7(GND) BIT0.NC@8(GND) BIT1.NC@1(GND) BIT1.NC@2(GND) BIT1.NC@3(GND) BIT1.NC@4(GND) BIT1.NC@5(GND) BIT1.NC@6(GND) BIT1.NC@7(GND) BIT1.NC@8(GND) BIT2.NC@1(GND) BIT2.NC@2(GND) BIT2.NC@3(GND) BIT2.NC@4(GND) BIT2.NC@5(GND) BIT2.NC@6(GND) BIT2.NC@7(GND) BIT2.NC@8(GND) BIT3.NC@1(GND) BIT3.NC@2(GND) BIT3.NC@3(GND) BIT3.NC@4(GND) BIT3.NC@5(GND) BIT3.NC@6(GND) BIT3.NC@7(GND) BIT3.NC@8(GND) CW.NC@1(GND) CW.NC@2(GND) CW.NC@3(GND) CW.NC@4(GND) CW.NC@5(GND) CW.NC@6(GND) CW.NC@7(GND) CW.NC@8(GND) CYL1.NC@1(GND) CYL1.NC@2(GND) CYL1.NC@3(GND) CYL1.NC@4(GND) CYL1.NC@5(GND) CYL1.NC@6(GND) CYL1.NC@7(GND) CYL1.NC@8(GND) CYL2.NC@1(GND) CYL2.NC@2(GND) CYL2.NC@3(GND) CYL2.NC@4(GND) CYL2.NC@5(GND) CYL2.NC@6(GND) CYL2.NC@7(GND) CYL2.NC@8(GND) CYL4.NC@1(GND) CYL4.NC@2(GND) CYL4.NC@3(GND) CYL4.NC@4(GND) CYL4.NC@5(GND) CYL4.NC@6(GND) CYL4.NC@7(GND) CYL4.NC@8(GND) CYL8.NC@1(GND) CYL8.NC@2(GND) CYL8.NC@3(GND) CYL8.NC@4(GND) CYL8.NC@5(GND) CYL8.NC@6(GND) CYL8.NC@7(GND) CYL8.NC@8(GND) CYL16.NC@1(GND) CYL16.NC@2(GND) CYL16.NC@3(GND) CYL16.NC@4(GND) CYL16.NC@5(GND) CYL16.NC@6(GND) CYL16.NC@7(GND) CYL16.NC@8(GND) CYL32.NC@1(GND) CYL32.NC@2(GND) CYL32.NC@3(GND) CYL32.NC@4(GND) CYL32.NC@5(GND) CYL32.NC@6(GND) CYL32.NC@7(GND) CYL32.NC@8(GND) CYL64.NC@1(GND) CYL64.NC@2(GND) CYL64.NC@3(GND) CYL64.NC@4(GND) CYL64.NC@5(GND) CYL64.NC@6(GND) CYL64.NC@7(GND) CYL64.NC@8(GND) CYL128.NC@1(GND) CYL128.NC@2(GND) CYL128.NC@3(GND) CYL128.NC@4(GND) CYL128.NC@5(GND) CYL128.NC@6(GND) CYL128.NC@7(GND) CYL128.NC@8(GND) DC_ERASE.NC@1(GND) DC_ERASE.NC@2(GND) DC_ERASE.NC@3(GND) DC_ERASE.NC@4(GND) DC_ERASE.NC@5(GND) DC_ERASE.NC@6(GND) DC_ERASE.NC@7(GND) DC_ERASE.NC@8(GND) E1.7(P:GND) E2.7(P:GND) E3.8(GND) E4.7(P:GND) E5.7(P:GND) E6.7(P:GND) E7.7(P:GND) E8.8(P:GND) E10.7(P:GND) E11.7(P:GND) E12.7(P:GND) E13.4(PWR:GND) E14.8(P:GND) E15.7(P:GND) E16.7(P:GND) E17.7(P:GND) E18.7(P:GND) E19.8(GND) E20.8(GND) E21.4(PWR:GND) E22.4(PWR:GND) E23.7(P:GND) E24.7(P:GND) E26.7(P:GND) E27.7(P:GND) E28.7(P:GND) E29.7(P:GND) E30.4(PWR:GND) E31.4(PWR:GND) E32.4(PWR:GND) E33.4(PWR:GND) E34.4(PWR:GND) FWD/REV.NC@1(GND) FWD/REV.NC@2(GND) FWD/REV.NC@3(GND) FWD/REV.NC@4(GND) FWD/REV.NC@5(GND) FWD/REV.NC@6(GND) FWD/REV.NC@7(GND) FWD/REV.NC@8(GND) HEAD.NC@1(GND) HEAD.NC@2(GND) HEAD.NC@3(GND) HEAD.NC@4(GND) HEAD.NC@5(GND) HEAD.NC@6(GND) HEAD.NC@7(GND) HEAD.NC@8(GND) RTZ.NC@1(GND) RTZ.NC@2(GND) RTZ.NC@3(GND) RTZ.NC@4(GND) RTZ.NC@5(GND) RTZ.NC@6(GND) RTZ.NC@7(GND) RTZ.NC@8(GND) RUN.NC@1(GND) RUN.NC@2(GND) RUN.NC@3(GND) RUN.NC@4(GND) RUN.NC@5(GND) RUN.NC@6(GND) RUN.NC@7(GND) RUN.NC@8(GND) WRITE.NC@1(GND) WRITE.NC@2(GND) WRITE.NC@3(GND) WRITE.NC@4(GND) WRITE.NC@5(GND) WRITE.NC@6(GND) WRITE.NC@7(GND) WRITE.NC@8(GND)
VCC: E1.14(P:VCC) E2.14(P:VCC) E3.16(VCC) E4.14(P:VCC) E5.14(P:VCC) E6.14(P:VCC) E7.14(P:VCC) E8.16(P:VCC) E10.14(P:VCC) E11.14(P:VCC) E12.14(P:VCC) E13.8(PWR:VCC) E14.16(P:VCC) E15.14(P:VCC) E16.14(P:VCC) E17.14(P:VCC) E18.14(P:VCC) E19.16(VCC) E20.16(VCC) E21.8(PWR:VCC) E22.8(PWR:VCC) E23.14(P:VCC) E24.14(P:VCC) E26.14(P:VCC) E27.14(P:VCC) E28.14(P:VCC) E29.14(P:VCC) E30.8(PWR:VCC) E31.8(PWR:VCC) E32.8(PWR:VCC) E33.8(PWR:VCC) E34.8(PWR:VCC)

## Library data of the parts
ADDR_INV POWER_ON SEEK_INC = dec-con:BULB: T 1 3/4 Bulb
BIT0 BIT1-BIT3 CW CYL1 CYL2 CYL4 CYL8 CYL16 CYL32 CYL64 CYL128 DC_ERASE FWD/REV HEAD RTZ RUN WRITE = switch:710X: 710x with optional V2 or V3 mounting bracket.
C1-C43 C53 C62 C63 = rcl:C-US: CAPACITOR, American symbol
C44 C45 C52 C60 C61 C67 C68 = rcl:CPOL-US: POLARIZED CAPACITOR, American symbol
D1-D4 = diode:1N4148: DIODE
D5 = diode:ZENER-DIODE: Z-Diode
DRIVE FUNCTION SECTOR = switch:CK101X12: ROTARY SWITCH C&K
E1 E16 E23 = 74xx-jameco:74*10: Triple 3-input NAND gate
E2 E5 E11 E18 = 74xx-jameco:74*74: Dual D type positive edge triggered FLIP FLOP, preset and clear
E3 = 74xx-jameco:74*42: 4-line to 10-line DECODER (1-of-10)
E4 E24 = 74xx-jameco:74*20: Dual 4-input NAND gate
E6 E12 = 74xx-jameco:74*04: Hex INVERTER
E7 E10 E15 E17 E26-E29 = 74xx-jameco:74*00: Quad 2-input NAND gate
E8 E14 = 74xx-jameco:74*123: Retriggerable monostable MULTIVIBRATOR
E13 E21 E22 E30-E34 = 74xx-jameco:DS75451
E19 E20 = 74xx-jameco:74*193: Synchronous 4-bit UP/DOWN COUNTER
E25 = linear:*741: OP AMP
J1 J2 = dec-con:DEC40PINS: 40 pin ribbon connector for BC08, BC11 cables.
POWER = con-amp:FLOPPY-4: MATE N-LOCK
Q1 = transistor-small-signal:2N4870: UNIJUNCTION TRANSISTOR
R1-R8 R10-R46 R50 R69 R70 R147 R148 = rcl:R-US_: RESISTOR, American symbol
R9 = pot:TRIM_EU-: POTENTIOMETER
RN1-RN8 = resistor-sil:GE09R: SIL RESISTOR

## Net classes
0 default: width 0.508 mm, drill 0.279 mm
